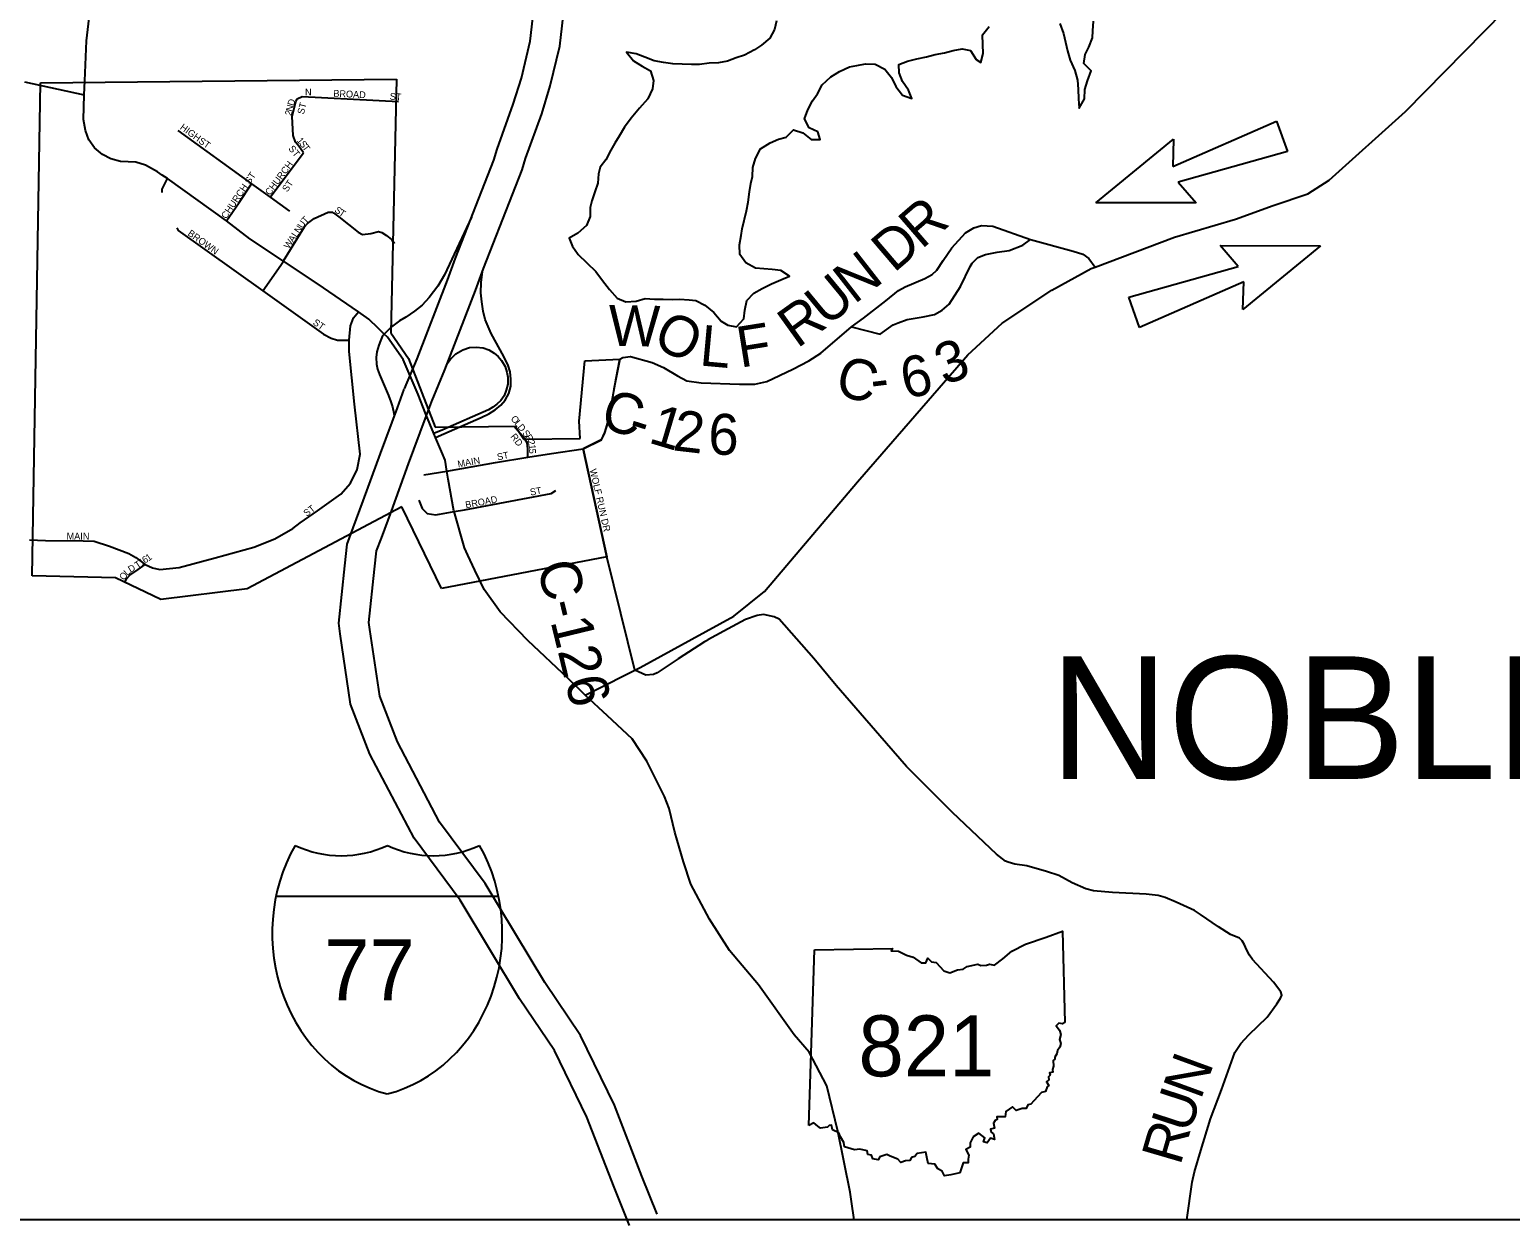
# Model space of a CAD drawing. Extents: x -452339 to 6403467, y -1 to 1814750.
# Drawn here: x -60980 to -50105, y 1597924 to 1606675 of the extents above; entities that cross this region are included whole.
import ezdxf

# ---------------------------------------------------------------- set-up
doc = ezdxf.new("R2010")
doc.units = 0
for name, color, linetype in [('Default', 7, 'Continuous'), ('GM_X_County', 7, 'Continuous'), ('GM_X_County_Road', 7, 'Continuous'), ('GM_X_Minor_Lake', 7, 'Continuous'), ('GM_X_Minor_Lake_Text', 7, 'Continuous'), ('GM_X_Minor_River', 7, 'Continuous'), ('GM_X_Minor_River_Text', 7, 'Continuous'), ('GM_X_Township_Subdivision', 7, 'Continuous'), ('GM_X_Township_Subdivision_Text', 7, 'Continuous')]:
    doc.layers.add(name, color=color, linetype=linetype)

msp = doc.modelspace()

# ---------------------------------------------------------------- linework, layer by layer
at = {"layer": 'Default'}
for p, q in [((-52585, 1605669), (-51822, 1606003)), ((-51822, 1606003), (-51742, 1605780)), ((-53149, 1605404), (-52580, 1605870)), ((-52580, 1605870), (-52585, 1605669)), ((-51742, 1605780), (-52545, 1605556)), ((-52545, 1605556), (-52414, 1605403)), ((-52414, 1605403), (-53149, 1605404)), ((-52104, 1604935), (-52236, 1605089)), ((-52236, 1605089), (-51500, 1605088)), ((-51500, 1605088), (-52069, 1604621)), ((-52907, 1604711), (-52104, 1604935)), ((-52064, 1604823), (-52828, 1604488)), ((-52069, 1604621), (-52064, 1604823)), ((-52828, 1604488), (-52907, 1604711)), ((-55257, 1598627), (-55216, 1599918)), ((-33348, 1597935), (-90726, 1597935))]:
    msp.add_line(p, q, dxfattribs=at)
for points in [[(-60573, 1606300), (-60561, 1606593), (-60538, 1606802), (-60519, 1607037), (-60460, 1607290), (-60389, 1607589), (-60333, 1607822), (-60318, 1607927)], [(-56900, 1601787), (-56832, 1601823), (-56536, 1601971), (-56496, 1601992), (-56117, 1602200), (-55807, 1602369), (-55583, 1602550), (-54899, 1603355), (-54089, 1604287), (-53837, 1604520), (-53472, 1604763), (-53184, 1604921), (-53155, 1604931), (-52573, 1605151), (-52123, 1605283), (-51847, 1605384), (-51593, 1605470), (-51435, 1605571), (-50876, 1606075), (-50152, 1606812), (-49304, 1607670)], [(-60578, 1606196), (-60578, 1606196), (-60573, 1606300)], [(-60006, 1605606), (-60041, 1605630), (-60129, 1605680), (-60199, 1605703), (-60311, 1605706), (-60382, 1605727), (-60444, 1605758), (-60502, 1605807), (-60544, 1605866), (-60570, 1605935), (-60583, 1606016), (-60578, 1606196)], [(-58565, 1604604), (-58867, 1604811), (-59116, 1604975), (-59363, 1605138), (-59534, 1605271), (-59967, 1605581), (-60006, 1605606)], [(-54943, 1604493), (-54943, 1604493), (-54855, 1604557), (-54691, 1604683), (-54599, 1604760), (-54549, 1604786), (-54405, 1604848), (-54351, 1604878), (-54317, 1604908), (-54272, 1604980), (-54208, 1605073), (-54106, 1605183), (-54046, 1605221), (-53990, 1605237), (-53906, 1605233), (-53630, 1605134)], [(-54943, 1604493), (-54733, 1604439), (-54637, 1604507), (-54601, 1604523), (-54535, 1604546), (-54417, 1604566), (-54335, 1604584), (-54279, 1604616), (-54227, 1604660), (-54143, 1604788), (-54072, 1604937), (-54058, 1604961), (-54016, 1605001), (-53960, 1605023), (-53874, 1605041), (-53786, 1605053), (-53686, 1605093), (-53630, 1605134)], [(-53630, 1605134), (-53316, 1605048), (-53244, 1605026), (-53202, 1604994), (-53155, 1604931)], [(-58069, 1603852), (-58126, 1603996), (-58236, 1604252), (-58352, 1604416), (-58375, 1604439), (-58420, 1604483), (-58488, 1604550), (-58565, 1604604)], [(-56646, 1604256), (-56646, 1604256), (-56624, 1604268), (-56566, 1604276), (-56408, 1604232), (-56324, 1604193), (-56222, 1604133), (-56152, 1604097), (-56048, 1604081), (-55766, 1604071), (-55654, 1604071), (-55566, 1604091), (-55376, 1604182), (-55257, 1604242), (-55169, 1604300), (-54943, 1604493)], [(-57905, 1603374), (-57916, 1603434), (-57929, 1603513), (-57956, 1603577), (-58000, 1603680), (-58012, 1603709), (-58069, 1603852)], [(-57709, 1602707), (-57761, 1602817), (-57785, 1602869), (-57863, 1603136), (-57865, 1603142), (-57905, 1603374)], [(-56536, 1601971), (-56740, 1602805)], [(-56900, 1601787), (-57024, 1601911), (-57320, 1602189), (-57524, 1602399), (-57642, 1602565), (-57709, 1602707)], [(-51784, 1599584), (-51784, 1599584), (-51790, 1599610), (-51846, 1599680), (-52000, 1599848), (-52022, 1599880), (-52042, 1599920), (-52058, 1599954), (-52074, 1599984), (-52094, 1600004), (-52160, 1600030), (-52248, 1600086), (-52380, 1600177), (-52426, 1600207), (-52560, 1600269), (-52640, 1600303), (-52692, 1600317), (-52780, 1600327), (-53028, 1600339), (-53166, 1600352), (-53224, 1600366), (-53324, 1600410), (-53422, 1600464), (-53512, 1600494), (-53656, 1600536), (-53744, 1600548), (-53794, 1600562), (-53814, 1600568), (-53878, 1600620), (-54202, 1600926), (-54540, 1601264), (-54736, 1601490), (-55057, 1601859), (-55221, 1602057), (-55475, 1602347), (-55511, 1602363), (-55591, 1602381), (-55637, 1602373), (-55723, 1602343), (-55881, 1602259), (-55998, 1602194)], [(-55998, 1602194), (-56000, 1602193), (-56023, 1602180), (-56216, 1602054), (-56370, 1601952), (-56398, 1601940), (-56454, 1601936), (-56536, 1601971)], [(-55216, 1599918), (-54643, 1599927), (-54652, 1599911), (-54598, 1599908), (-54541, 1599880), (-54492, 1599863), (-54433, 1599822), (-54398, 1599822), (-54383, 1599856), (-54356, 1599830), (-54323, 1599825), (-54267, 1599763), (-54221, 1599750), (-54166, 1599771), (-54125, 1599775), (-54095, 1599796), (-54016, 1599813), (-53994, 1599803), (-53953, 1599805), (-53931, 1599813), (-53895, 1599806), (-53832, 1599853), (-53766, 1599908), (-53665, 1599960), (-53514, 1600010), (-53394, 1600054), (-53377, 1599384)], [(-52482, 1597935), (-52442, 1598213), (-52425, 1598289), (-52379, 1598445), (-52307, 1598676), (-52227, 1598890), (-52129, 1599163), (-52085, 1599229), (-52027, 1599295), (-51892, 1599423), (-51820, 1599522), (-51794, 1599562), (-51784, 1599584)], [(-53377, 1599384), (-53395, 1599375), (-53422, 1599379), (-53440, 1599360), (-53417, 1599329), (-53407, 1599296), (-53416, 1599259), (-53407, 1599229), (-53413, 1599204), (-53430, 1599179), (-53436, 1599155), (-53451, 1599130), (-53450, 1599116), (-53464, 1599105), (-53461, 1599063), (-53469, 1599039), (-53466, 1599019), (-53489, 1599014), (-53484, 1598998), (-53498, 1598985), (-53495, 1598963), (-53511, 1598949), (-53496, 1598921), (-53508, 1598912), (-53519, 1598877), (-53548, 1598870), (-53606, 1598808), (-53627, 1598784), (-53649, 1598779), (-53662, 1598754), (-53691, 1598754), (-53734, 1598737), (-53762, 1598766), (-53810, 1598731), (-53816, 1598691), (-53877, 1598692), (-53875, 1598672), (-53889, 1598666), (-53901, 1598646), (-53894, 1598609), (-53923, 1598600), (-53919, 1598579), (-53901, 1598567), (-53893, 1598526), (-53923, 1598534), (-53948, 1598500), (-53974, 1598508), (-53966, 1598537), (-54010, 1598572), (-54051, 1598544), (-54072, 1598500), (-54073, 1598470), (-54104, 1598452), (-54083, 1598410), (-54087, 1598381), (-54087, 1598354), (-54125, 1598355), (-54149, 1598281)], [(-54149, 1598281), (-54215, 1598266), (-54261, 1598258), (-54278, 1598292), (-54311, 1598310), (-54333, 1598343), (-54380, 1598348), (-54391, 1598395), (-54397, 1598432), (-54462, 1598423), (-54479, 1598400), (-54503, 1598394), (-54516, 1598370), (-54548, 1598368), (-54582, 1598357), (-54604, 1598380), (-54659, 1598403), (-54684, 1598415), (-54736, 1598397), (-54747, 1598375), (-54788, 1598384), (-54798, 1598409), (-54823, 1598416), (-54829, 1598442), (-54882, 1598455), (-54923, 1598450), (-54995, 1598471), (-55000, 1598504), (-55025, 1598546), (-55037, 1598574), (-55083, 1598596), (-55092, 1598630), (-55107, 1598629), (-55120, 1598615), (-55171, 1598609), (-55191, 1598623), (-55220, 1598647), (-55257, 1598627)]]:
    msp.add_lwpolyline(points, dxfattribs=at)
for centre, major_axis, start_param, end_param in [((-58108, 1600040), (0, -1211), 4.15077, 6.05619), ((-58691, 1601575), (0, -966), 5.88324, 6.683049), ((-58598, 1600040), (0, -1211), 0.227007, 2.13242), ((-58014, 1601575), (0, -966), 5.883359, 6.683012)]:
    msp.add_ellipse(centre, major_axis=major_axis, ratio=0.9, start_param=start_param, end_param=end_param, dxfattribs=at)
at = {"layer": 'GM_X_County_Road'}
for p, q in [((-58279, 1603897), (-58229, 1604034)), ((-58073, 1603821), (-58022, 1603958)), ((-58403, 1603562), (-58279, 1603897)), ((-58196, 1603486), (-58073, 1603821)), ((-58530, 1603216), (-58403, 1603562)), ((-58323, 1603140), (-58196, 1603486)), ((-58603, 1603018), (-58530, 1603216)), ((-58396, 1602942), (-58323, 1603140))]:
    msp.add_line(p, q, dxfattribs=at)
for points in [[(-58024, 1603953), (-57930, 1604177), (-57705, 1604759), (-57647, 1604920), (-57363, 1605645), (-57337, 1605728), (-57219, 1606057), (-57156, 1606262), (-57087, 1606553), (-57035, 1607005), (-57040, 1607824), (-57101, 1608973), (-57187, 1610182), (-57265, 1611589), (-57379, 1613474), (-57506, 1615703)], [(-58227, 1604038), (-58134, 1604259), (-57911, 1604836), (-57853, 1604997), (-57571, 1605717), (-57546, 1605798), (-57428, 1606127), (-57368, 1606320), (-57304, 1606591), (-57255, 1607017), (-57260, 1607818), (-57320, 1608959), (-57407, 1610168), (-57485, 1611576), (-57598, 1613461), (-57725, 1615691)], [(-61017, 1606293), (-60578, 1606196)], [(-58664, 1602737), (-58647, 1602897), (-58603, 1603018)], [(-58446, 1602713), (-58431, 1602847), (-58396, 1602942)], [(-58698, 1602238), (-58710, 1602316), (-58664, 1602737)], [(-58481, 1602270), (-58488, 1602321), (-58446, 1602713)], [(-56575, 1597894), (-56688, 1598176), (-56887, 1598689), (-57126, 1599178), (-57381, 1599559), (-57818, 1600283), (-58156, 1600739), (-58480, 1601354), (-58622, 1601723), (-58698, 1602238)], [(-56371, 1597976), (-56484, 1598257), (-56685, 1598777), (-56935, 1599288), (-57196, 1599677), (-57635, 1600405), (-57969, 1600856), (-58279, 1601445), (-58408, 1601780), (-58481, 1602270)], [(-54943, 1598070), (-54954, 1598139), (-55044, 1598586), (-55126, 1598920), (-55254, 1599166), (-55366, 1599295), (-55628, 1599662), (-55839, 1599912), (-55986, 1600144), (-56123, 1600400), (-56177, 1600564), (-56224, 1600724), (-56241, 1600783), (-56282, 1600957), (-56318, 1601043), (-56448, 1601303), (-56554, 1601467), (-56736, 1601637), (-56900, 1601787)], [(-54924, 1597935), (-54943, 1598070)]]:
    msp.add_lwpolyline(points, dxfattribs=at)
at = {"layer": 'GM_X_Minor_Lake'}
for points in [[(-59026, 1605850), (-59043, 1605897), (-59051, 1606037), (-59024, 1606146), (-59014, 1606166)], [(-59014, 1606166), (-58979, 1606185), (-58270, 1606148)], [(-59891, 1605934), (-59349, 1605544), (-59212, 1605445), (-59070, 1605342)], [(-58969, 1605770), (-59002, 1605820), (-59026, 1605850)], [(-59212, 1605445), (-58969, 1605770)], [(-60007, 1605480), (-60007, 1605504), (-59967, 1605581)], [(-59441, 1605407), (-59349, 1605544)], [(-59534, 1605271), (-59441, 1605407), (-59441, 1605407)], [(-59114, 1604977), (-58960, 1605226), (-58939, 1605252), (-58889, 1605289), (-58788, 1605334), (-58756, 1605335), (-58750, 1605330)], [(-58750, 1605330), (-58749, 1605329), (-58709, 1605301), (-58568, 1605187), (-58536, 1605171), (-58474, 1605178), (-58418, 1605193), (-58392, 1605185), (-58358, 1605164), (-58322, 1605134), (-58309, 1605112), (-58303, 1605111), (-58298, 1605115)], [(-59899, 1605219), (-59889, 1605201), (-59268, 1604756), (-58822, 1604439), (-58766, 1604409), (-58718, 1604396), (-58633, 1604395)], [(-59268, 1604756), (-59135, 1604945), (-59116, 1604975), (-59115, 1604976), (-59114, 1604977)], [(-60980, 1602928), (-60864, 1602924), (-60586, 1602921), (-60506, 1602919), (-60392, 1602883), (-60250, 1602829), (-60200, 1602799), (-60130, 1602747), (-60078, 1602723), (-60024, 1602711), (-59882, 1602725), (-59618, 1602796), (-59332, 1602876), (-59180, 1602937), (-59046, 1603013), (-58992, 1603053), (-58865, 1603141), (-58695, 1603264), (-58623, 1603344), (-58575, 1603446), (-58553, 1603558), (-58593, 1603925), (-58632, 1604311), (-58633, 1604395), (-58622, 1604500), (-58602, 1604558), (-58565, 1604604)], [(-56914, 1603598), (-56781, 1603664), (-56756, 1603716), (-56746, 1603749), (-56720, 1603834), (-56697, 1603979), (-56673, 1604115), (-56646, 1604256)], [(-57322, 1603536), (-57321, 1603598), (-57325, 1603640), (-57346, 1603673), (-57421, 1603761)], [(-57558, 1603496), (-57322, 1603536), (-57148, 1603562)], [(-57148, 1603562), (-56914, 1603598)], [(-56740, 1602805), (-56914, 1603598)], [(-58084, 1603405), (-57916, 1603434), (-57558, 1603496)], [(-58121, 1603219), (-58098, 1603159), (-58060, 1603123), (-57996, 1603112), (-57971, 1603117)], [(-57971, 1603117), (-57970, 1603117), (-57863, 1603136), (-57787, 1603149), (-57149, 1603268), (-57115, 1603290)], [(-60280, 1602617), (-60266, 1602644), (-60244, 1602670), (-60199, 1602699), (-60130, 1602747)]]:
    msp.add_lwpolyline(points, dxfattribs=at)
at = {"layer": 'GM_X_Minor_Lake_Text'}
msp.add_line((-59167, 1600312), (-57536, 1600312), dxfattribs=at)
for points in [[(-55494, 1606741), (-55509, 1606675), (-55544, 1606612), (-55606, 1606562), (-55657, 1606527), (-55729, 1606488), (-55791, 1606467), (-55854, 1606443), (-55920, 1606432), (-55990, 1606429), (-56060, 1606418), (-56118, 1606418), (-56188, 1606421), (-56256, 1606424), (-56324, 1606434), (-56392, 1606445), (-56461, 1606472), (-56525, 1606497), (-56597, 1606509), (-56544, 1606447), (-56482, 1606406), (-56420, 1606373), (-56397, 1606301), (-56406, 1606241), (-56439, 1606168), (-56501, 1606099), (-56562, 1606025), (-56611, 1605958), (-56649, 1605894), (-56682, 1605841), (-56711, 1605791), (-56747, 1605720), (-56790, 1605666), (-56802, 1605616), (-56807, 1605548), (-56830, 1605485), (-56852, 1605419), (-56863, 1605369), (-56864, 1605303), (-56890, 1605238), (-56953, 1605180), (-57017, 1605143), (-56994, 1605083), (-56979, 1605063)], [(-54029, 1606455), (-53995, 1606433), (-53976, 1606499), (-53980, 1606567), (-53981, 1606637), (-53932, 1606698)], [(-53414, 1606721), (-53387, 1606648), (-53373, 1606582), (-53358, 1606520), (-53337, 1606450), (-53305, 1606376), (-53284, 1606304), (-53279, 1606238), (-53276, 1606166), (-53272, 1606098), (-53232, 1606167), (-53231, 1606235), (-53212, 1606299), (-53185, 1606372), (-53239, 1606427), (-53228, 1606493), (-53200, 1606546), (-53175, 1606614), (-53172, 1606666), (-53168, 1606738)], [(-55719, 1604963), (-55764, 1605024), (-55767, 1605096), (-55753, 1605163), (-55746, 1605213), (-55715, 1605345), (-55702, 1605409), (-55693, 1605484), (-55683, 1605546), (-55670, 1605596), (-55668, 1605664), (-55649, 1605730), (-55612, 1605801), (-55542, 1605844), (-55481, 1605870), (-55423, 1605885), (-55371, 1605939), (-55301, 1605918), (-55239, 1605869), (-55175, 1605868), (-55191, 1605925), (-55256, 1605953), (-55288, 1606020), (-55265, 1606087), (-55230, 1606153), (-55194, 1606204), (-55159, 1606270), (-55095, 1606329), (-55032, 1606368), (-54958, 1606402), (-54906, 1606413), (-54841, 1606424), (-54771, 1606422), (-54700, 1606385), (-54650, 1606324), (-54619, 1606258), (-54570, 1606194), (-54500, 1606169), (-54525, 1606231), (-54569, 1606295), (-54594, 1606358), (-54597, 1606418), (-54533, 1606443), (-54465, 1606460), (-54393, 1606475), (-54329, 1606493), (-54260, 1606506), (-54198, 1606523), (-54132, 1606535), (-54070, 1606522), (-54029, 1606455)], [(-56979, 1605063), (-56951, 1605023), (-56887, 1604962), (-56822, 1604899), (-56772, 1604833), (-56721, 1604766), (-56666, 1604704), (-56600, 1604677), (-56526, 1604682), (-56460, 1604701), (-56390, 1604695), (-56328, 1604696), (-56262, 1604693), (-56208, 1604695), (-56136, 1604692), (-56086, 1604685), (-56022, 1604651), (-55955, 1604598), (-55901, 1604534), (-55851, 1604505), (-55788, 1604492), (-55735, 1604552), (-55728, 1604614), (-55712, 1604685), (-55661, 1604741), (-55599, 1604774), (-55532, 1604809), (-55464, 1604837), (-55400, 1604866), (-55463, 1604906), (-55527, 1604913), (-55587, 1604918), (-55649, 1604924), (-55719, 1604963)]]:
    msp.add_lwpolyline(points, dxfattribs=at)
at = {"layer": 'GM_X_Minor_River_Text'}
for p, q in [((-60962, 1602664), (-60900, 1606284)), ((-60900, 1606284), (-58285, 1606311)), ((-58285, 1606311), (-58328, 1604449)), ((-58328, 1604449), (-58198, 1604260)), ((-58198, 1604260), (-58002, 1603757)), ((-56944, 1603801), (-56902, 1604242)), ((-56902, 1604242), (-56646, 1604256)), ((-56646, 1604256), (-56689, 1604035)), ((-56689, 1604035), (-56720, 1603832)), ((-58002, 1603757), (-57415, 1603763)), ((-57415, 1603763), (-57351, 1603669)), ((-56936, 1603673), (-56944, 1603801)), ((-56720, 1603832), (-56757, 1603715)), ((-57351, 1603669), (-56936, 1603673)), ((-56782, 1603663), (-56914, 1603598)), ((-56757, 1603715), (-56782, 1603663)), ((-56914, 1603598), (-56740, 1602805)), ((-58245, 1603171), (-59382, 1602568)), ((-57955, 1602571), (-58245, 1603171)), ((-56740, 1602805), (-57955, 1602571)), ((-60350, 1602650), (-60962, 1602664)), ((-60017, 1602491), (-60350, 1602650)), ((-59382, 1602568), (-60017, 1602491))]:
    msp.add_line(p, q, dxfattribs=at)
at = {"layer": 'GM_X_Township_Subdivision'}
for points in [[(-57735, 1605298), (-57934, 1604875), (-57983, 1604791), (-58045, 1604709), (-58096, 1604653), (-58154, 1604608), (-58217, 1604564), (-58263, 1604538), (-58321, 1604493), (-58375, 1604439)], [(-58000, 1603680), (-57937, 1603706), (-57821, 1603758), (-57664, 1603826), (-57607, 1603855), (-57560, 1603884), (-57518, 1603918), (-57488, 1603955), (-57461, 1604004), (-57445, 1604058), (-57445, 1604109), (-57451, 1604162), (-57465, 1604209), (-57496, 1604274), (-57591, 1604445), (-57613, 1604495), (-57633, 1604546), (-57649, 1604608), (-57659, 1604676), (-57666, 1604742), (-57664, 1604819), (-57654, 1604899)], [(-58375, 1604439), (-58387, 1604426), (-58404, 1604390), (-58415, 1604358), (-58430, 1604310), (-58435, 1604268), (-58433, 1604219), (-58424, 1604183), (-58409, 1604144), (-58345, 1603988), (-58327, 1603942), (-58315, 1603905), (-58305, 1603860), (-58302, 1603835)], [(-57911, 1604225), (-57888, 1604256), (-57849, 1604295), (-57799, 1604325), (-57749, 1604341), (-57701, 1604344), (-57650, 1604338), (-57608, 1604323), (-57568, 1604300), (-57538, 1604276), (-57515, 1604246), (-57487, 1604202), (-57474, 1604161), (-57467, 1604122), (-57468, 1604072), (-57479, 1604027), (-57495, 1603985), (-57519, 1603953), (-57548, 1603924), (-57577, 1603902), (-57610, 1603884), (-57944, 1603736), (-58012, 1603709)]]:
    msp.add_lwpolyline(points, dxfattribs=at)

# ---------------------------------------------------------------- texts
at = {"layer": 'Default'}
for s, p in [('77', (-58816, 1599548)), ('821', (-54893, 1598989))]:
    msp.add_text(s, height=447.7, dxfattribs=at).set_placement(p)
at = {"layer": 'GM_X_County'}
for s, rotation, p in [('R', 40.8254, (-54430, 1605057)), ('D', 40.4787, (-54633, 1604884)), ('N', 37.9088, (-54924, 1604654)), ('U', 39.5671, (-55125, 1604487)), ('W', 358.8739, (-56731, 1604354)), ('R', 35.6808, (-55343, 1604330)), ('O', 334.3277, (-56416, 1604355)), ('L', 354.7876, (-56066, 1604210)), ('F', 9.0926, (-55761, 1604192)), ('3', 20.3601, (-54263, 1604061)), ('6', 11.6746, (-54549, 1603963)), ('C', 346.1465, (-55075, 1603996)), ('-', 6.9111, (-54789, 1603955)), ('C', 342.2019, (-56802, 1603760)), ('1', 343.3517, (-56444, 1603645)), ('2', 353.3579, (-56263, 1603587)), ('6', 358.2651, (-55999, 1603557)), ('-', 342.3963, (-56600, 1603681)), ('C-126', 283.6351, (-57255, 1602743)), ('N', 69.898, (-52380, 1598811)), ('U', 71.8254, (-52462, 1598562)), ('R', 73.6884, (-52530, 1598328))]:
    msp.add_text(s, height=300, rotation=rotation, dxfattribs=at).set_placement(p)
at = {"layer": 'GM_X_Minor_River'}
for s, rotation, p in [('N', 0, (-58957, 1606192)), ('D', 74.0816, (-59040, 1606112)), ('ST', 75.9573, (-58966, 1606050)), ('BROAD', 357.0909, (-58750, 1606183)), ('ST', 356.1879, (-58336, 1606161)), ('2', 75.9335, (-59058, 1606040)), ('N', 75.916, (-59051, 1606070)), ('HIGH', 324.0898, (-59880, 1605948)), ('ST', 325.3092, (-59744, 1605847)), ('ST', 309.0829, (-59082, 1605800)), ('1', 309.8056, (-59021, 1605859)), ('S', 307.7168, (-59002, 1605836)), ('T', 306.411, (-58980, 1605808)), ('CHURCH', 53.3211, (-59215, 1605454)), ('CHURCH ST', 55.904, (-59536, 1605281)), ('ST', 55.2978, (-59088, 1605479)), ('S', 322.7312, (-58745, 1605341)), ('U', 56.5766, (-58975, 1605212)), ('T', 46.3331, (-58952, 1605247)), ('T', 326.094, (-58714, 1605318)), ('BROWN', 324.4633, (-59823, 1605169)), ('A', 56.5811, (-59043, 1605109)), ('L', 56.5752, (-59019, 1605146)), ('N', 56.5811, (-58999, 1605175)), ('W', 56.5757, (-59075, 1605061)), ('ST', 325.3092, (-58904, 1604514)), ('O', 308.7281, (-57450, 1603817)), ('L', 308.7013, (-57422, 1603783)), ('D', 308.7219, (-57400, 1603755)), ('RD', 307.4135, (-57451, 1603686)), ('S', 308.7281, (-57365, 1603711)), ('R', 302.4507, (-57343, 1603684)), ('2', 287.6353, (-57324, 1603654)), ('MAIN', 10.7134, (-57832, 1603459)), ('ST', 10.6147, (-57542, 1603512)), ('1', 275.4403, (-57315, 1603627)), ('5', 270.5932, (-57312, 1603598)), ('WOLF RUN DR', 282.8582, (-56867, 1603444)), ('ST', 10.6279, (-57300, 1603253)), ('BROAD', 10.6227, (-57775, 1603160)), ('ST', 37.5735, (-58945, 1603097)), ('MAIN', 0, (-60708, 1602931)), ('T', 33.6249, (-60188, 1602716)), ('1', 34.1427, (-60158, 1602736)), ('6', 34.1145, (-60133, 1602753)), ('1', 34.1366, (-60107, 1602770)), ('O', 55.2551, (-60285, 1602628)), ('L', 44.1305, (-60261, 1602662)), ('D', 31.2524, (-60238, 1602685))]:
    msp.add_text(s, height=50, rotation=rotation, dxfattribs=at).set_placement(p)
at = {"layer": 'GM_X_Township_Subdivision_Text'}
msp.add_text('NOBLE', height=900, rotation=0, dxfattribs=at).set_placement((-53487, 1601173))

doc.saveas('drawing.dxf')
